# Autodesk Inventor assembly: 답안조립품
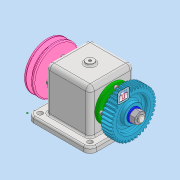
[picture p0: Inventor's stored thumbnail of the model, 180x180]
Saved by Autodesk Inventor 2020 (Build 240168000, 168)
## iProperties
Created: 2022-07
Part Number: 답안조립품
Document SubType Name: Assembly
Designer: MIRAE
Author: MIRAE
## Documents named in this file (12)
- C:\Users\MIRAE\Desktop\720706V1006\답안조립품.iam
- C:\Users\MIRAE\Desktop\720706V1006\본체.ipt
- C:\Users\MIRAE\Desktop\720706V1006\축.ipt
- C:\Users\MIRAE\Desktop\720706V1006\키 5x5.ipt
- C:\Users\MIRAE\Desktop\720706V1006\스퍼기어.ipt
- C:\Users\MIRAE\Desktop\720706V1006\V벨트풀리.ipt
- C:\Users\MIRAE\Desktop\720706V1006\와셔 12x24.ipt
- C:\Users\MIRAE\Desktop\720706V1006\너트 M12x1.25.ipt
- C:\Users\MIRAE\Desktop\720706V1006\베어링 6204.ipt
- C:\Users\MIRAE\Desktop\720706V1006\커버.ipt
- C:\Users\MIRAE\Desktop\720706V1006\오일실 20x35x8.ipt
- C:\Users\MIRAE\Desktop\720706V1006\볼트 M4x0.7.ipt
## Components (1 placed, 1 different names)
1. V벨트풀리:1 — 각도:2
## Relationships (1: Angle 1)
- 각도:2 [Angle]: V벨트풀리:1
